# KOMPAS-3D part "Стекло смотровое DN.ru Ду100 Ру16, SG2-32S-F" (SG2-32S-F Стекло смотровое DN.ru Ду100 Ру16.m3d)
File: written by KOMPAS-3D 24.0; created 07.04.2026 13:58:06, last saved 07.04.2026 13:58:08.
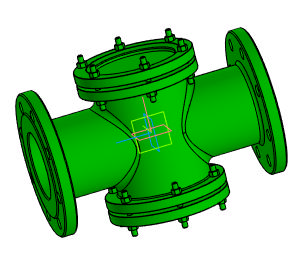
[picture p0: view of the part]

Document properties: Автор: Main; Полное имя файла: D:\DN.ru Аутсерс\Стекло смотровое DN.ru\SG2-32S-F Стекло смотровое DN.ru Ду100 Ру16\SG2-32S-FСтекло смотровое DN.ru Ду100 Ру16.m3d

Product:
- Body: Тело 1  | qty 1
    Масса: 25.876303
- Part/product: Стекло смотровое DN.ru Ду100 Ру16  | designation SG2-32S-F
    Масса: 26
    Раздел спецификации: Прочие изделия
    Примечание: D500-00111

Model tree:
1. Операция без истории:1

Expressions: SG2-32S-F
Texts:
  Точка начала. Х
  Точка начала. Y
  Точка начала. Z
